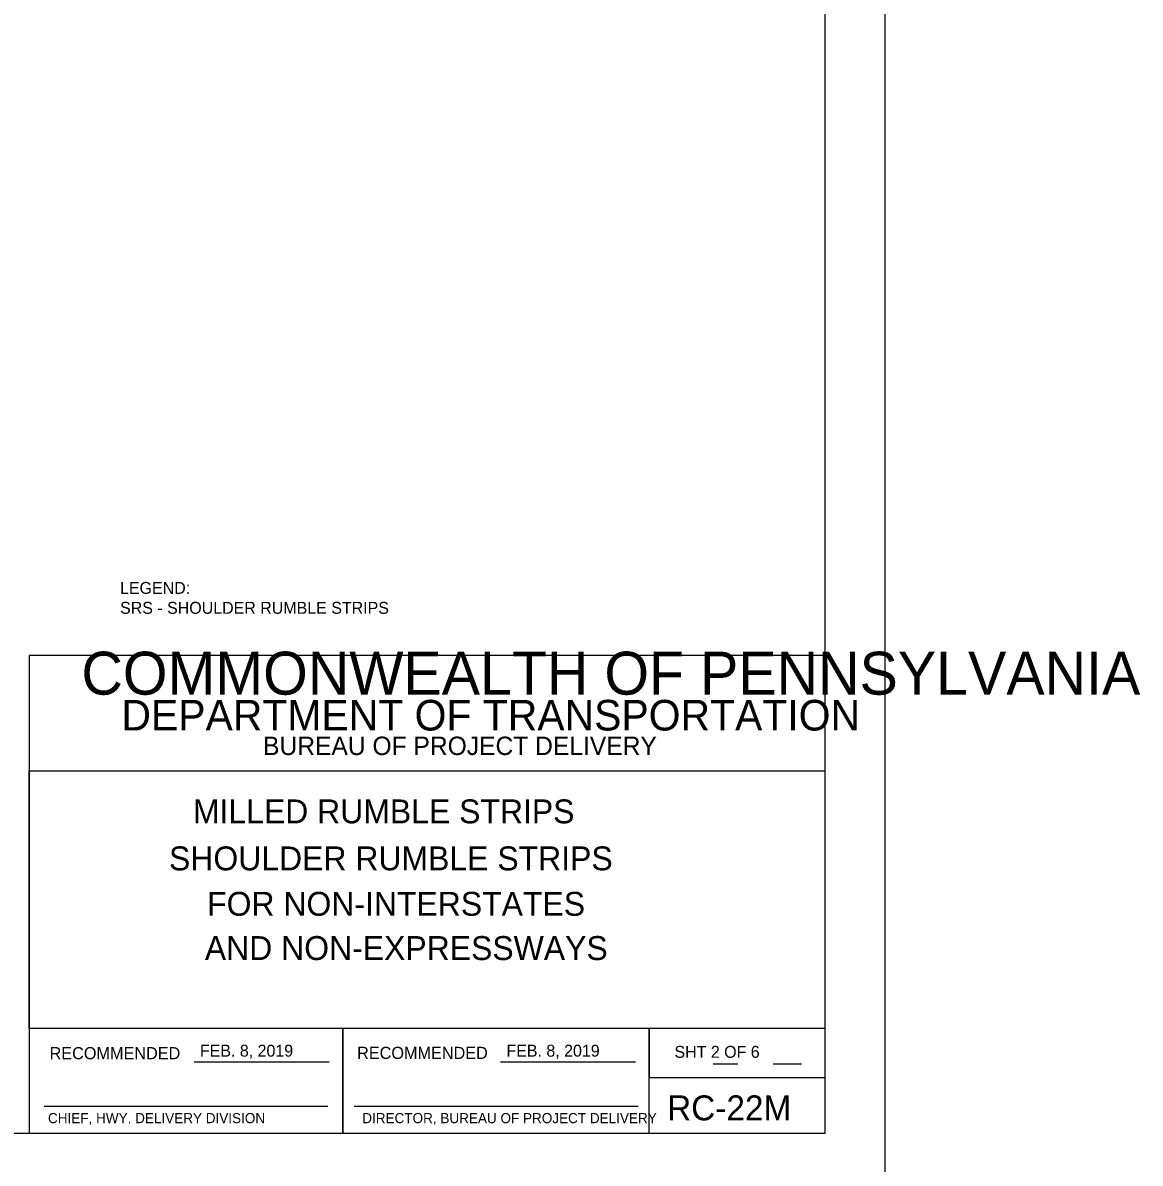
# Model space of a CAD drawing. Extents: x 632008 to 634206, y 294231 to 297795.
# Drawn here: x 632632.3 to 632913, y 296614.1 to 296900.5 of the extents above; entities that cross this region are included whole.
import ezdxf

# ---------------------------------------------------------------- set-up
doc = ezdxf.new("R2010")
doc.units = 0
doc.layers.add('1', color=7, linetype='Continuous')
doc.layers.add('PLT-BNDY', color=7, linetype='Continuous')

msp = doc.modelspace()

# ---------------------------------------------------------------- linework, layer by layer
at = {"layer": '1'}
for p, q in [((632833.86, 296640.5), (632833.86, 296703.33)), ((632675.32, 296639.61), (632709.21, 296639.61)), ((632752.32, 296639.61), (632786.19, 296639.61)), ((632805.73, 296639.05), (632811.87, 296639.05)), ((632820.79, 296639.05), (632827.89, 296639.05)), ((632637.64, 296628.43), (632708.89, 296628.43)), ((632715.49, 296628.43), (632786.83, 296628.43))]:
    msp.add_line(p, q, dxfattribs=at)
msp.add_lwpolyline([(632833.86, 296621.62), (632833.86, 297185.62), (632047.86, 297185.62), (632047.86, 296621.62), (632833.86, 296621.62), (632833.86, 296647.98), (632633.86, 296647.98), (632633.86, 296712.66), (632833.86, 296712.66), (632833.86, 296741.62), (632633.86, 296741.62), (632633.86, 296621.62), (632712.66, 296621.62), (632712.66, 296647.98), (632712.66, 296621.62), (632789.66, 296621.62), (632789.66, 296647.98), (632789.66, 296635.66), (632833.86, 296635.66)], dxfattribs=at)
at = {"layer": 'PLT-BNDY'}
msp.add_lwpolyline([(632007.86, 297200.62), (632848.86, 297200.62), (632848.86, 296606.62), (632007.86, 296606.62)], close=True, dxfattribs=at)

# ---------------------------------------------------------------- texts
at = {"layer": '1'}
for s, height, p in [('LEGEND:', 3, (632656.72, 296757.07)), ('SRS - SHOULDER RUMBLE STRIPS', 3, (632656.72, 296752.07)), ('COMMONWEALTH OF PENNSYLVANIA', 10.7834, (632647.01, 296731.77)), ('DEPARTMENT OF TRANSPORTATION', 7.6843, (632657.07, 296722.77)), ('BUREAU OF PROJECT DELIVERY', 4.6221, (632692.65, 296716.61)), ('MILLED RUMBLE STRIPS', 6, (632675.02, 296699.46)), ('SHOULDER RUMBLE STRIPS', 6, (632669.02, 296687.66)), ('FOR NON-INTERSTATES', 6, (632678.59, 296676.25)), ('AND NON-EXPRESSWAYS', 6, (632678.02, 296665.14)), ('FEB. 8, 2019', 3, (632676.78, 296640.87)), ('FEB. 8, 2019', 3, (632753.78, 296640.87)), ('RECOMMENDED', 3.048, (632639.02, 296640.22)), ('RECOMMENDED', 3.048, (632716.27, 296640.3)), ('SHT 2 OF 6', 3, (632795.99, 296640.58)), ('RC-22M', 6.267, (632794.14, 296624.88))]:
    msp.add_text(s, height=height, dxfattribs=at).set_placement(p)
for s, p in [('CHIEF, HWY. DELIVERY DIVISION', (632638.62, 296624.17)), ('DIRECTOR, BUREAU OF PROJECT DELIVERY', (632717.56, 296624.17))]:
    msp.add_text(s, height=2.54, rotation=360, dxfattribs=at).set_placement(p)

doc.saveas('drawing.dxf')
